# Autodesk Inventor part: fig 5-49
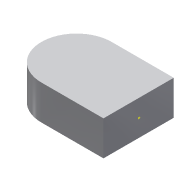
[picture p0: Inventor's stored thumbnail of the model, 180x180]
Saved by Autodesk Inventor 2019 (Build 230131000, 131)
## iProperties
Created: 2010-02
Part Number: fig 5-49
Document SubType Name: Modeling
Designer: CADSoft
Density: 1 g/cm^3
Material: Generic
Appearance: Default
Author: CADSoft
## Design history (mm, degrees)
sketch "Sketch1"
  geometry: L1 (-17.92, 20.292)-(0, 20.292); L2 (0, 20.292)-(0, 0); L3 (0, 0)-(-17.92, 0); A1 r 10.146 centre (-17.92, 10.146) between (-17.92, 20.292) and (-17.92, 0)
  constraints: 6 end point, 2 horizontal, 2 point on circle, 2 tangent, 1 centre point, 1 vertical
extrude "Extrusion1" new body sketch "Sketch1" distance "d0" = 10; taper "d1" = 0 deg
workpoint "Work Point1"
body "Solid1"
